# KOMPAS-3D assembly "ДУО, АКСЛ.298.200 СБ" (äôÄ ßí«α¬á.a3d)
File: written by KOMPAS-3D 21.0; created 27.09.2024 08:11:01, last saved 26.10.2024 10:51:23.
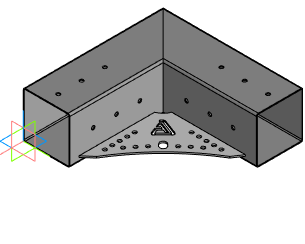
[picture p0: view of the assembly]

Document properties: Полное имя файла: C:\Users\Алексей Бочаров\YandexDisk\Соединения бруса\Соединения бруса\ДУО\ДУО сборка.a3d; Автор: Алексей Бочаров

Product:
- Part/product: ДУО  | designation АКСЛ.298.200 СБ
    Масса: 3.338231
    Форматы листов документа: A4
    source file: АКСЛ.298.200 - ДУО.spw, ДУО спецификация.spw
  - Component [detail]: Профиль L = 300 мм  | designation АКСЛ.298.302-01  | pos. 3  | Масса: 1.514806; source file: ..\ТРИО\АКСЛ.298.302-01 - Профиль L = 300 мм.cdw, ..\ТРИО\Профиль L = 300 мм (2).m3d
  - Component [detail]: Профиль L = 300 мм  | designation АКСЛ.298.302  | pos. 2  | Масса: 1.514806; Форматы листов документа: A2; source file: ..\ТРИО\АКСЛ.298.302 - Профиль L = 300 мм.cdw, ..\ТРИО\Профиль L = 300 мм (1).m3d
  - Component [assembly]: Перемычка  | designation АКСЛ.298.201  | pos. 1  | Масса: 0.308618; source file: ..\Перемычка.stp

Referenced files: АКСЛ.298.200 СБ>Деталь (локальная).m3d
Referenced files in C:\Users\79253\YandexDisk\Соединения бруса\Соединения бруса\: Перемычка.stp
Referenced files in C:\Users\79253\YandexDisk\Соединения бруса\Соединения бруса\ТРИО\: Профиль L = 300 мм (1).m3d, Профиль L = 300 мм (2).m3d
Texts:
  АКСЛ.298.200 СБ
  АКСЛ.298.201 Перемычка
  АКСЛ.298.302 Профиль L = 300 мм
  АКСЛ.298.302-01 Профиль L = 300 мм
